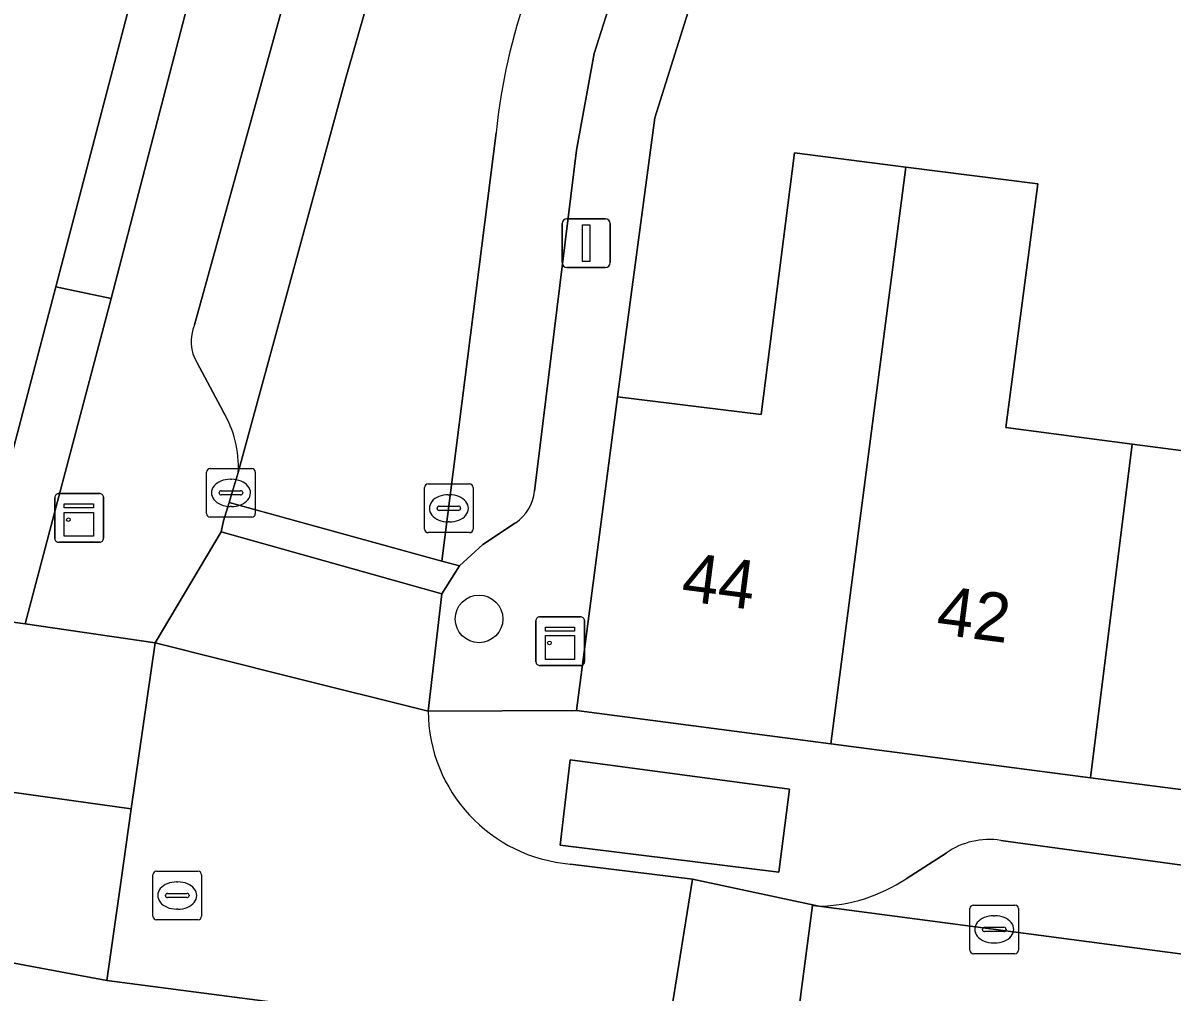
# Model space of a CAD drawing. Extents: x 161838 to 162344, y 381620 to 382160.
# Drawn here: x 161912.46 to 161936.08, y 381708.64 to 381728.55 of the extents above; entities that cross this region are included whole.
import ezdxf

# ---------------------------------------------------------------- set-up
doc = ezdxf.new("R2010")
doc.units = 0
for name, color, linetype in [('IMGEO_Boom', 7, 'Continuous'), ('IMGEO_Erf', 7, 'Continuous'), ('IMGEO_Hek', 7, 'Continuous'), ('IMGEO_Kast', 7, 'Continuous'), ('IMGEO_Kolk', 7, 'Continuous'), ('IMGEO_Lichtmast', 7, 'Continuous'), ('IMGEO_Muur', 7, 'Continuous'), ('IMGEO_Pand', 7, 'Continuous'), ('IMGEO_Pand_nummerreeks', 7, 'Continuous'), ('IMGEO_Parkeervlak_open', 7, 'Continuous'), ('IMGEO_Rijbaan_lokaal_open', 7, 'Continuous'), ('IMGEO_Rioolput', 7, 'Continuous'), ('IMGEO_Voetpad_open', 7, 'Continuous')]:
    doc.layers.add(name, color=color, linetype=linetype)

msp = doc.modelspace()

# ---------------------------------------------------------------- linework, layer by layer
at = {"layer": 'IMGEO_Boom'}
msp.add_circle((161921.832, 381716.311), 0.489, dxfattribs=at)
at = {"layer": 'IMGEO_Erf'}
msp.add_lwpolyline([(161938.349, 381734.019), (161935.636, 381734.387), (161935.266, 381731.67), (161931.464, 381732.187), (161927.834, 381732.681), (161928.204, 381735.395), (161925.447, 381726.604), (161924.676, 381720.871), (161927.632, 381720.509), (161928.32, 381725.886), (161930.605, 381725.594), (161933.317, 381725.247), (161932.659, 381720.24), (161935.255, 381719.901), (161937.893, 381719.556)], dxfattribs=at)
at = {"layer": 'IMGEO_Hek'}
msp.add_lwpolyline([(161917.032, 381733.501), (161914.271, 381722.897)], dxfattribs=at)
at = {"layer": 'IMGEO_Kast'}
for p, q in [((161913.112, 381717.96), (161913.112, 381718.801)), ((161913.112, 381718.801), (161913.112, 381717.96)), ((161913.187, 381718.885), (161914.028, 381718.885)), ((161914.028, 381718.885), (161913.187, 381718.885)), ((161914.112, 381718.81), (161914.112, 381717.969)), ((161914.112, 381717.969), (161914.112, 381718.81)), ((161914.037, 381717.885), (161913.196, 381717.885)), ((161913.196, 381717.885), (161914.037, 381717.885)), ((161923.001, 381715.428), (161923.001, 381716.269)), ((161923.001, 381716.269), (161923.001, 381715.428)), ((161923.076, 381716.353), (161923.917, 381716.353)), ((161923.917, 381716.353), (161923.076, 381716.353)), ((161924.001, 381716.278), (161924.001, 381715.437)), ((161924.001, 381715.437), (161924.001, 381716.278)), ((161923.926, 381715.353), (161923.085, 381715.353)), ((161923.085, 381715.353), (161923.926, 381715.353))]:
    msp.add_line(p, q, dxfattribs=at)
for points in [[(161913.307, 381718.675), (161913.907, 381718.675), (161913.907, 381718.59), (161913.307, 381718.59), (161913.307, 381718.675)], [(161913.307, 381718.5), (161913.907, 381718.5), (161913.907, 381718.011), (161913.307, 381718.011), (161913.307, 381718.5)], [(161923.196, 381716.143), (161923.796, 381716.143), (161923.796, 381716.058), (161923.196, 381716.058), (161923.196, 381716.143)], [(161923.196, 381715.968), (161923.796, 381715.968), (161923.796, 381715.479), (161923.196, 381715.479), (161923.196, 381715.968)]]:
    msp.add_lwpolyline(points, dxfattribs=at)
for centre in [(161913.391, 381718.349), (161923.28, 381715.817)]:
    msp.add_circle(centre, 0.0377, dxfattribs=at)
for centre, start, end in [((161913.19, 381718.807), 92.4484, 184.2845), ((161913.19, 381718.807), 92.4484, 184.2845), ((161914.034, 381718.807), 2.4484, 94.2845), ((161914.034, 381718.807), 2.4484, 94.2845), ((161913.19, 381717.963), 182.4484, 274.2845), ((161913.19, 381717.963), 182.4484, 274.2845), ((161914.034, 381717.963), 272.4484, 4.2845), ((161914.034, 381717.963), 272.4484, 4.2845), ((161923.079, 381716.275), 92.4484, 184.2845), ((161923.079, 381716.275), 92.4484, 184.2845), ((161923.923, 381716.275), 2.4484, 94.2845), ((161923.923, 381716.275), 2.4484, 94.2845), ((161923.079, 381715.431), 182.4484, 274.2845), ((161923.079, 381715.431), 182.4484, 274.2845), ((161923.923, 381715.431), 272.4484, 4.2845), ((161923.923, 381715.431), 272.4484, 4.2845)]:
    msp.add_arc(centre, 0.0779, start, end, dxfattribs=at)
at = {"layer": 'IMGEO_Kolk'}
for p, q in [((161916.232, 381718.474), (161916.232, 381719.326)), ((161916.307, 381719.4), (161917.159, 381719.4)), ((161917.233, 381719.326), (161917.233, 381718.474)), ((161916.72, 381719.18), (161916.745, 381719.18)), ((161920.711, 381718.157), (161920.711, 381719.009)), ((161920.786, 381719.083), (161921.638, 381719.083)), ((161921.712, 381719.009), (161921.712, 381718.157)), ((161916.491, 381718.894), (161916.491, 381718.906)), ((161916.929, 381718.857), (161916.531, 381718.857)), ((161916.534, 381718.943), (161916.932, 381718.943)), ((161916.975, 381718.906), (161916.975, 381718.894)), ((161921.199, 381718.863), (161921.224, 381718.863)), ((161916.743, 381718.62), (161916.718, 381718.62)), ((161920.97, 381718.577), (161920.97, 381718.589)), ((161921.408, 381718.54), (161921.01, 381718.54)), ((161921.013, 381718.626), (161921.411, 381718.626)), ((161921.454, 381718.589), (161921.454, 381718.577)), ((161917.159, 381718.4), (161916.307, 381718.4)), ((161921.222, 381718.303), (161921.197, 381718.303)), ((161921.638, 381718.083), (161920.786, 381718.083)), ((161931.922, 381709.505), (161931.922, 381710.357)), ((161931.997, 381710.431), (161932.849, 381710.431)), ((161932.923, 381710.357), (161932.923, 381709.505)), ((161932.41, 381710.211), (161932.435, 381710.211)), ((161932.181, 381709.925), (161932.181, 381709.937)), ((161932.619, 381709.888), (161932.221, 381709.888)), ((161932.224, 381709.974), (161932.622, 381709.974)), ((161932.665, 381709.937), (161932.665, 381709.925)), ((161932.433, 381709.651), (161932.408, 381709.651)), ((161932.849, 381709.431), (161931.997, 381709.431))]:
    msp.add_line(p, q, dxfattribs=at)
for points in [[(161916.232, 381718.474), (161916.232, 381719.326)], [(161916.307, 381719.4), (161917.159, 381719.4)], [(161917.233, 381719.326), (161917.233, 381718.474)], [(161920.711, 381718.157), (161920.711, 381719.009)], [(161920.786, 381719.083), (161921.638, 381719.083)], [(161921.712, 381719.009), (161921.712, 381718.157)], [(161917.159, 381718.4), (161916.307, 381718.4)], [(161921.638, 381718.083), (161920.786, 381718.083)], [(161931.922, 381709.505), (161931.922, 381710.357)], [(161931.997, 381710.431), (161932.849, 381710.431)], [(161932.923, 381710.357), (161932.923, 381709.505)], [(161932.849, 381709.431), (161931.997, 381709.431)]]:
    msp.add_lwpolyline(points, dxfattribs=at)
for centre, radius, start, end in [((161916.309, 381719.324), 0.0765, 91.552, 178.448), ((161916.309, 381719.324), 0.0765, 91.552, 178.448), ((161917.157, 381719.324), 0.0765, 1.552, 88.448), ((161917.157, 381719.324), 0.0765, 1.552, 88.448), ((161920.788, 381719.007), 0.0765, 91.552, 178.448), ((161920.788, 381719.007), 0.0765, 91.552, 178.448), ((161921.636, 381719.007), 0.0765, 1.552, 88.448), ((161921.636, 381719.007), 0.0765, 1.552, 88.448), ((161916.531, 381718.903), 0.0403, 85.8775, 175.7526), ((161916.528, 381718.893), 0.0366, 178.938, 274.7102), ((161916.932, 381718.9), 0.043, 264.8664, 352.4533), ((161916.936, 381718.905), 0.0386, 1.7309, 96.639), ((161921.01, 381718.586), 0.0403, 85.8775, 175.7526), ((161921.007, 381718.576), 0.0366, 178.938, 274.7102), ((161921.411, 381718.583), 0.043, 264.8664, 352.4533), ((161921.415, 381718.588), 0.0386, 1.7309, 96.639), ((161916.309, 381718.476), 0.0765, 181.552, 268.448), ((161916.309, 381718.476), 0.0765, 181.552, 268.448), ((161917.157, 381718.476), 0.0765, 271.552, 358.448), ((161917.157, 381718.476), 0.0765, 271.552, 358.448), ((161920.788, 381718.159), 0.0765, 181.552, 268.448), ((161920.788, 381718.159), 0.0765, 181.552, 268.448), ((161921.636, 381718.159), 0.0765, 271.552, 358.448), ((161921.636, 381718.159), 0.0765, 271.552, 358.448), ((161931.999, 381710.355), 0.0765, 91.552, 178.448), ((161931.999, 381710.355), 0.0765, 91.552, 178.448), ((161932.847, 381710.355), 0.0765, 1.552, 88.448), ((161932.847, 381710.355), 0.0765, 1.552, 88.448), ((161932.221, 381709.934), 0.0403, 85.8775, 175.7526), ((161932.218, 381709.924), 0.0366, 178.938, 274.7102), ((161932.622, 381709.931), 0.043, 264.8664, 352.4533), ((161932.626, 381709.936), 0.0386, 1.7309, 96.639), ((161931.999, 381709.507), 0.0765, 181.552, 268.448), ((161931.999, 381709.507), 0.0765, 181.552, 268.448), ((161932.847, 381709.507), 0.0765, 271.552, 358.448), ((161932.847, 381709.507), 0.0765, 271.552, 358.448)]:
    msp.add_arc(centre, radius, start, end, dxfattribs=at)
for centre, major_axis, ratio, start_param, end_param in [((161916.719, 381718.9), (-0.387, 0.002), 0.722429, 4.712389, 7.853982), ((161916.744, 381718.9), (-0.39, 0.002), 0.717154, 1.570796, 4.712389), ((161921.198, 381718.583), (-0.387, 0.002), 0.722429, 4.712389, 7.853982), ((161921.223, 381718.583), (-0.39, 0.002), 0.717154, 1.570796, 4.712389), ((161932.409, 381709.931), (-0.387, 0.002), 0.722429, 4.712389, 7.853982), ((161932.434, 381709.931), (-0.39, 0.002), 0.717154, 1.570796, 4.712389)]:
    msp.add_ellipse(centre, major_axis=major_axis, ratio=ratio, start_param=start_param, end_param=end_param, dxfattribs=at)
at = {"layer": 'IMGEO_Lichtmast'}
for p, q in [((161923.539, 381723.632), (161923.539, 381724.432)), ((161923.539, 381724.432), (161923.539, 381723.632)), ((161923.639, 381724.532), (161924.429, 381724.532)), ((161924.429, 381724.532), (161923.639, 381724.532)), ((161924.529, 381724.432), (161924.529, 381723.632)), ((161924.529, 381723.632), (161924.529, 381724.432)), ((161924.429, 381723.532), (161923.639, 381723.532)), ((161923.639, 381723.532), (161924.429, 381723.532))]:
    msp.add_line(p, q, dxfattribs=at)
msp.add_lwpolyline([(161923.959, 381724.407), (161924.109, 381724.407), (161924.109, 381723.657), (161923.959, 381723.657), (161923.959, 381724.407)], dxfattribs=at)
for centre, start, end in [((161923.639, 381724.432), 90, 180), ((161923.639, 381724.432), 90, 180), ((161924.429, 381724.432), 0, 90), ((161924.429, 381724.432), 360, 90), ((161923.639, 381723.632), 180, 270), ((161923.639, 381723.632), 180, 270), ((161924.429, 381723.632), 270, 0), ((161924.429, 381723.632), 270, 0)]:
    msp.add_arc(centre, 0.1, start, end, dxfattribs=at)
at = {"layer": 'IMGEO_Muur'}
msp.add_lwpolyline([(161924.676, 381720.871), (161925.447, 381726.604), (161928.204, 381735.395)], dxfattribs=at)
at = {"layer": 'IMGEO_Pand'}
msp.add_lwpolyline([(161912.06, 381719.035), (161913.133, 381723.134), (161915.922, 381733.787), (161911.085, 381735.053)], dxfattribs=at)
for points in [[(161930.605, 381725.594), (161928.32, 381725.886), (161927.632, 381720.509), (161924.676, 381720.871), (161923.835, 381714.426), (161929.061, 381713.745)], [(161930.605, 381725.594), (161929.061, 381713.745), (161934.405, 381713.048), (161935.255, 381719.901), (161932.659, 381720.24), (161933.317, 381725.247)], [(161941.055, 381724.421), (161938.57, 381724.745), (161938.321, 381722.84), (161938.219, 381722.055), (161937.893, 381719.556), (161935.255, 381719.901), (161934.405, 381713.048), (161939.487, 381712.385)]]:
    msp.add_lwpolyline(points, close=True, dxfattribs=at)
at = {"layer": 'IMGEO_Parkeervlak_open'}
for points in [[(161930.019, 381773.8), (161929.028, 381768.381), (161928.167, 381764.412), (161925.871, 381755.689), (161925.028, 381752.783), (161924.159, 381750), (161919.692, 381735.743), (161915.985, 381722.354)], [(161916.883, 381719.321), (161919.084, 381727.401), (161920.816, 381733.424), (161927.557, 381755.075), (161928.855, 381760.062)], [(161922.974, 381718.936), (161923.837, 381725.942), (161924.196, 381727.931), (161931.251, 381750.082)], [(161922.182, 381726.301), (161921.068, 381717.499), (161921.433, 381717.398), (161921.913, 381717.842), (161922.585, 381718.282)], [(161916.037, 381721.571), (161916.572, 381720.573)], [(161941.923, 381710.484), (161932.56, 381711.759)], [(161931.432, 381711.498), (161930.61, 381710.972)], [(161928.816, 381710.405), (161954.008, 381707.086), (161955.333, 381706.911)]]:
    msp.add_lwpolyline(points, dxfattribs=at)
msp.add_lwpolyline([(161927.995, 381711.108), (161928.212, 381712.811), (161923.703, 381713.417), (161923.498, 381711.664)], close=True, dxfattribs=at)
for centre, radius, start, end in [((161934.786, 381724.996), 12.672, 160.5333, 174.0891), ((161916.761, 381722.012), 0.848, 156.2418, 211.3572), ((161914.656, 381719.432), 2.23, 357.1383, 30.7618), ((161922.057, 381719.039), 0.923, 304.9129, 353.5986), ((161932.32, 381710.23), 1.548, 81.068, 124.988), ((161928.735, 381713.782), 3.378, 271.3703, 303.7084)]:
    msp.add_arc(centre, radius, start, end, dxfattribs=at)
at = {"layer": 'IMGEO_Rijbaan_lokaal_open'}
for points in [[(161928.855, 381760.062), (161927.557, 381755.075), (161920.816, 381733.424), (161919.084, 381727.401), (161916.883, 381719.321), (161916.695, 381718.702), (161921.068, 381717.499), (161922.182, 381726.301)], [(161920.785, 381714.418), (161917.929, 381715.13), (161915.172, 381715.818), (161914.683, 381712.406), (161914.467, 381710.894), (161914.179, 381708.883), (161922.367, 381707.809), (161925.644, 381707.379), (161925.94, 381709.21), (161926.223, 381710.961), (161923.709, 381711.274)]]:
    msp.add_lwpolyline(points, dxfattribs=at)
for points in [[(161918.63, 381717.51), (161916.534, 381718.098), (161915.172, 381715.818), (161917.929, 381715.13), (161920.785, 381714.418), (161921.065, 381716.828)], [(161914.683, 381712.406), (161912.231, 381712.753), (161912.011, 381711.179), (161911.754, 381709.336), (161914.179, 381708.883), (161914.467, 381710.894)], [(161925.644, 381707.379), (161928.26, 381707.154), (161928.47, 381708.756), (161928.688, 381710.422), (161928.816, 381710.405), (161926.223, 381710.961), (161925.94, 381709.21)], [(161954.008, 381707.086), (161928.816, 381710.405), (161928.688, 381710.422), (161928.47, 381708.756), (161928.26, 381707.154), (161928.51, 381707.121), (161953.57, 381703.801)]]:
    msp.add_lwpolyline(points, close=True, dxfattribs=at)
for centre, radius, start, end in [((161934.786, 381724.996), 12.672, 160.5333, 174.0891), ((161923.964, 381714.443), 3.179, 180.4515, 265.3958)]:
    msp.add_arc(centre, radius, start, end, dxfattribs=at)
at = {"layer": 'IMGEO_Rioolput'}
for p, q in [((161915.128, 381710.201), (161915.128, 381711.053)), ((161915.203, 381711.127), (161916.055, 381711.127)), ((161916.129, 381711.053), (161916.129, 381710.201)), ((161915.616, 381710.907), (161915.641, 381710.907)), ((161915.387, 381710.621), (161915.387, 381710.633)), ((161915.825, 381710.584), (161915.427, 381710.584)), ((161915.43, 381710.67), (161915.828, 381710.67)), ((161915.871, 381710.633), (161915.871, 381710.621)), ((161915.639, 381710.347), (161915.614, 381710.347)), ((161916.055, 381710.127), (161915.203, 381710.127))]:
    msp.add_line(p, q, dxfattribs=at)
for points in [[(161915.128, 381710.201), (161915.128, 381711.053)], [(161915.203, 381711.127), (161916.055, 381711.127)], [(161916.129, 381711.053), (161916.129, 381710.201)], [(161916.055, 381710.127), (161915.203, 381710.127)]]:
    msp.add_lwpolyline(points, dxfattribs=at)
for centre, radius, start, end in [((161915.205, 381711.051), 0.0765, 91.552, 178.448), ((161915.205, 381711.051), 0.0765, 91.552, 178.448), ((161916.053, 381711.051), 0.0765, 1.552, 88.448), ((161916.053, 381711.051), 0.0765, 1.552, 88.448), ((161915.427, 381710.63), 0.0403, 85.8775, 175.7526), ((161915.424, 381710.62), 0.0366, 178.938, 274.7102), ((161915.828, 381710.627), 0.043, 264.8664, 352.4533), ((161915.832, 381710.632), 0.0386, 1.7309, 96.639), ((161915.205, 381710.203), 0.0765, 181.552, 268.448), ((161915.205, 381710.203), 0.0765, 181.552, 268.448), ((161916.053, 381710.203), 0.0765, 271.552, 358.448), ((161916.053, 381710.203), 0.0765, 271.552, 358.448)]:
    msp.add_arc(centre, radius, start, end, dxfattribs=at)
for centre, major_axis, ratio, start_param, end_param in [((161915.615, 381710.627), (-0.387, 0.002), 0.722429, 4.712389, 7.853982), ((161915.64, 381710.627), (-0.39, 0.002), 0.717154, 1.570796, 4.712389)]:
    msp.add_ellipse(centre, major_axis=major_axis, ratio=ratio, start_param=start_param, end_param=end_param, dxfattribs=at)
at = {"layer": 'IMGEO_Voetpad_open'}
for points in [[(161924.676, 381720.871), (161925.447, 381726.604), (161928.204, 381735.395), (161928.68, 381736.917), (161932.761, 381749.584), (161932.874, 381750), (161935.609, 381760.072), (161937.166, 381766.879), (161939.117, 381777.363), (161939.385, 381777.509), (161937.963, 381779.132)], [(161932.238, 381776.158), (161932.346, 381776.852), (161928.936, 381777.521), (161927.949, 381772.425), (161926.809, 381766.533), (161926.758, 381766.342), (161925.266, 381760.778), (161923.832, 381755.432), (161923.772, 381755.207), (161922.777, 381752.053), (161921.338, 381747.387), (161920.725, 381745.432), (161920.239, 381743.88), (161919.673, 381742.076), (161918.217, 381737.419), (161917.325, 381734.571), (161917.032, 381733.501), (161914.271, 381722.897), (161912.504, 381716.211), (161915.172, 381715.818), (161916.534, 381718.098), (161916.581, 381718.326), (161916.695, 381718.702), (161916.883, 381719.321)], [(161915.985, 381722.354), (161919.692, 381735.743), (161924.159, 381750)], [(161931.251, 381750.082), (161924.196, 381727.931), (161923.837, 381725.942), (161922.974, 381718.936)], [(161916.572, 381720.573), (161916.037, 381721.571)], [(161922.585, 381718.282), (161921.913, 381717.842), (161921.433, 381717.398), (161921.065, 381716.828), (161920.785, 381714.418), (161923.835, 381714.426), (161924.676, 381720.871)], [(161915.172, 381715.818), (161912.504, 381716.211), (161904.028, 381717.364), (161903.906, 381716.439), (161904.162, 381716.404), (161907.02, 381716.017)], [(161910.432, 381712.993), (161912.231, 381712.753), (161914.683, 381712.406), (161915.172, 381715.818)], [(161934.405, 381713.048), (161929.061, 381713.745), (161923.835, 381714.426), (161920.785, 381714.418)], [(162052.602, 381697.712), (162049.351, 381697.959), (162041.781, 381698.968), (162035.43, 381699.815), (162034.419, 381699.947), (162028.849, 381700.688), (162023.552, 381701.393), (162018.578, 381702.055), (162009.676, 381703.239), (162004.764, 381703.893), (162000, 381704.527), (161999.589, 381704.582), (161994.25, 381705.292), (161989.039, 381705.985), (161987.777, 381706.147), (161956.476, 381710.172), (161955.308, 381710.322), (161949.883, 381711.029), (161944.702, 381711.705), (161939.487, 381712.385), (161934.405, 381713.048)], [(161932.56, 381711.759), (161941.923, 381710.484)], [(161930.61, 381710.972), (161931.432, 381711.498)], [(161923.709, 381711.274), (161926.223, 381710.961), (161928.816, 381710.405)], [(161922.319, 381707.479), (161922.367, 381707.809), (161914.179, 381708.883), (161911.754, 381709.336), (161909.378, 381709.658)]]:
    msp.add_lwpolyline(points, dxfattribs=at)
for points in [[(161914.271, 381722.897), (161917.032, 381733.501), (161915.922, 381733.787), (161913.133, 381723.134)], [(161914.271, 381722.897), (161913.133, 381723.134), (161912.06, 381719.035), (161906.933, 381720.378), (161908.006, 381724.477), (161893.893, 381728.171), (161891.913, 381719.721), (161887.784, 381720.479), (161887.622, 381719.595), (161898.959, 381718.053), (161904.028, 381717.364), (161912.504, 381716.211)], [(161916.581, 381718.326), (161916.534, 381718.098), (161918.63, 381717.51), (161921.065, 381716.828), (161921.433, 381717.398), (161921.068, 381717.499), (161916.695, 381718.702)], [(161927.995, 381711.108), (161923.498, 381711.664), (161923.703, 381713.417), (161928.212, 381712.811)]]:
    msp.add_lwpolyline(points, close=True, dxfattribs=at)
for centre, radius, start, end in [((161916.761, 381722.012), 0.848, 156.2418, 211.3572), ((161914.656, 381719.432), 2.23, 357.1383, 30.7618), ((161922.057, 381719.039), 0.923, 304.9129, 353.5986), ((161923.964, 381714.443), 3.179, 180.4515, 265.3958), ((161932.32, 381710.23), 1.548, 81.068, 124.988), ((161928.735, 381713.782), 3.378, 271.3703, 303.7084)]:
    msp.add_arc(centre, radius, start, end, dxfattribs=at)

# ---------------------------------------------------------------- texts
at = {"layer": 'IMGEO_Pand_nummerreeks'}
for s, p in [('44', (161925.965, 381716.69)), ('42', (161931.207, 381716.006))]:
    msp.add_text(s, height=1, rotation=352.5707, dxfattribs=at).set_placement(p)

doc.saveas('drawing.dxf')
